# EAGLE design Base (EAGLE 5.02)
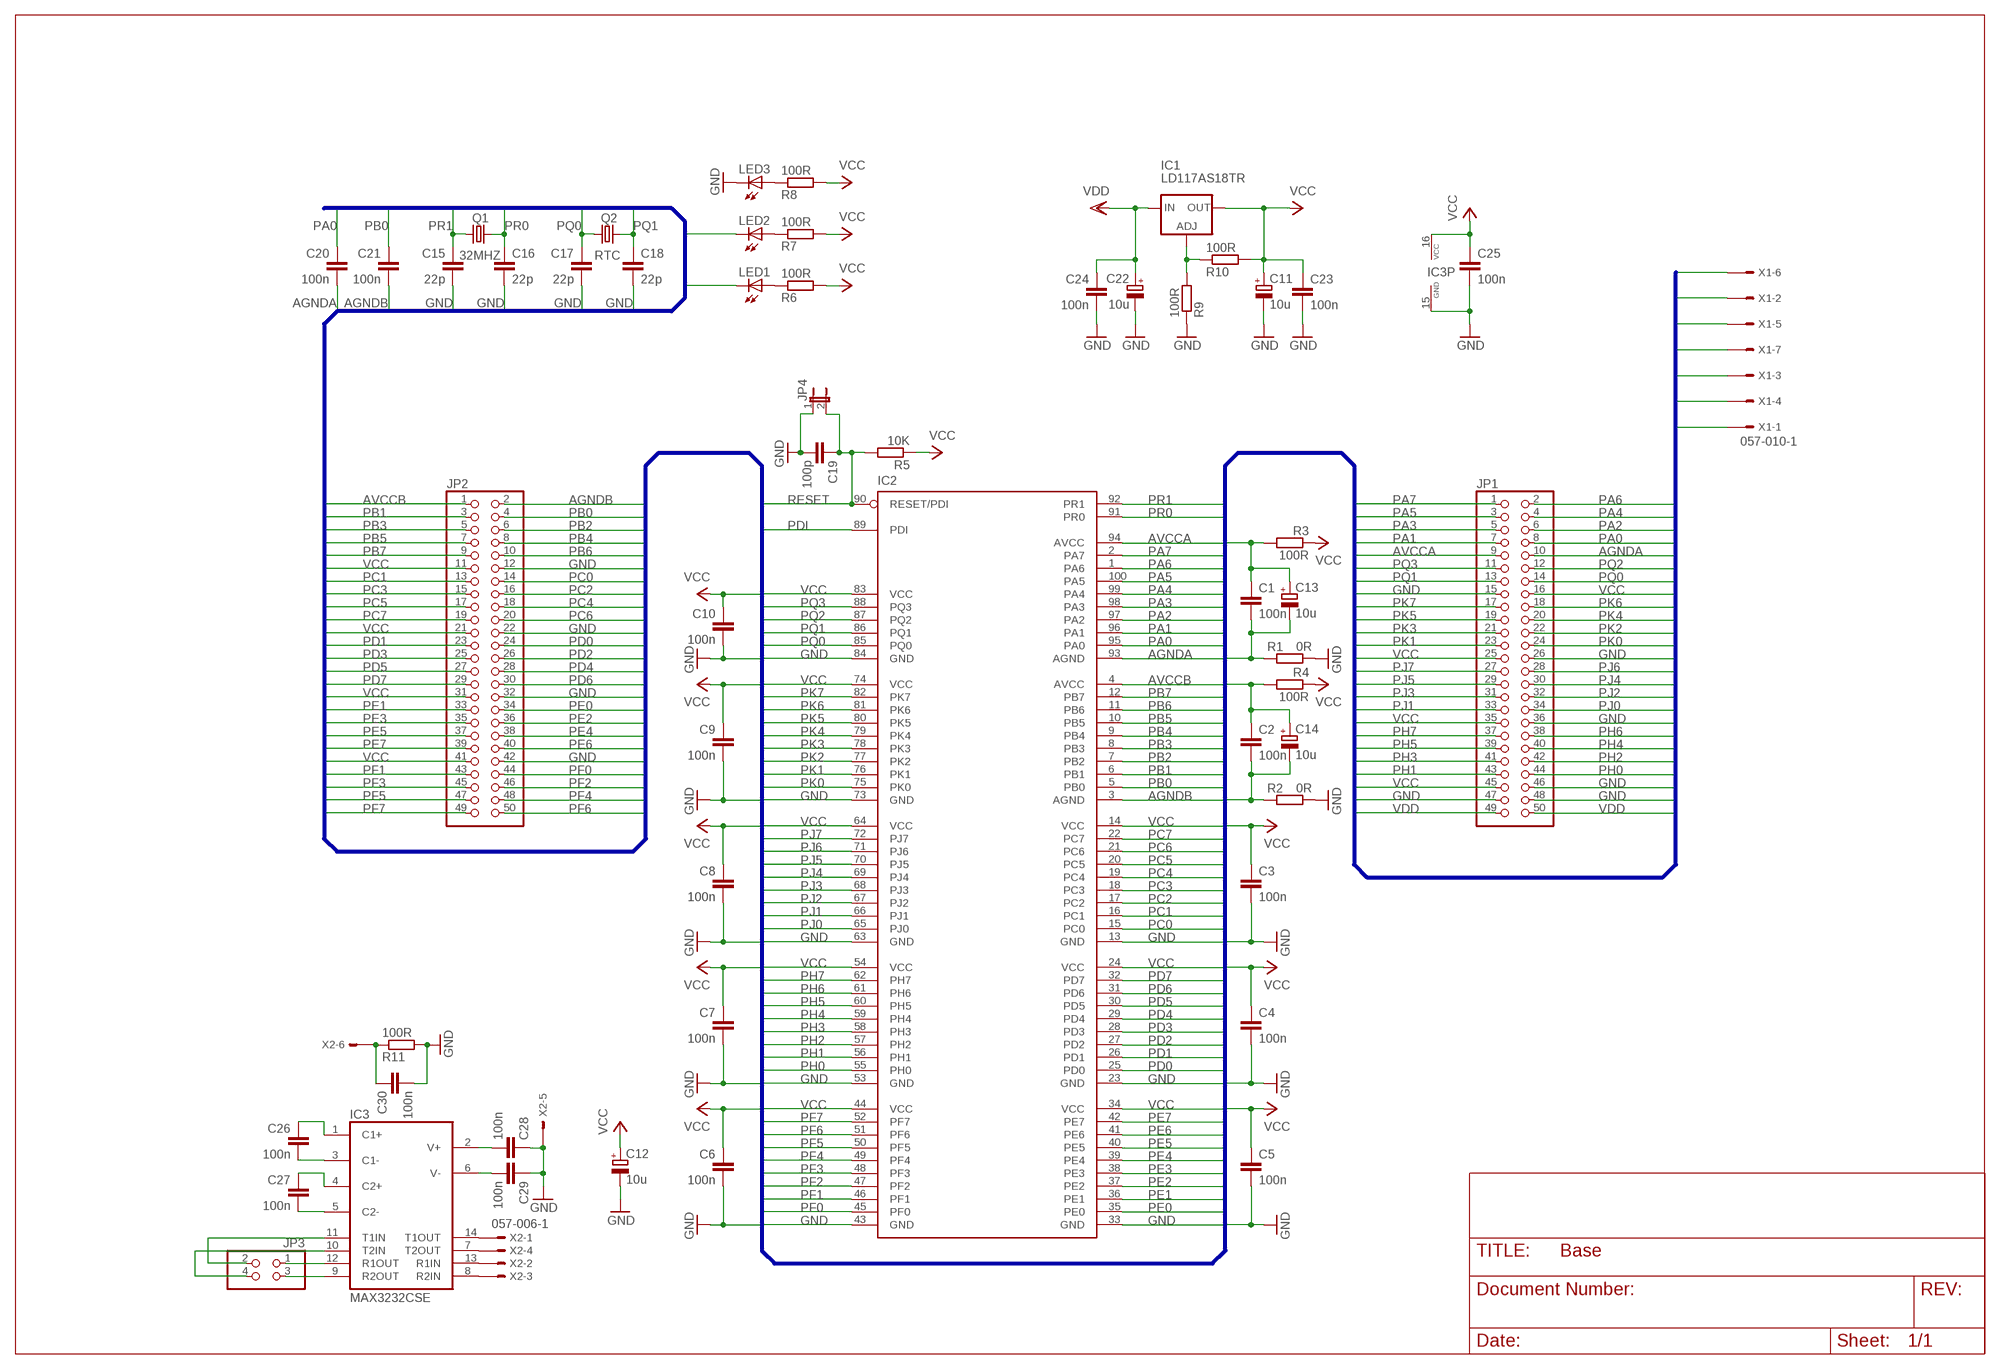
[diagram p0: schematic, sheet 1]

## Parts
C1  100n  C-EUC0603  [C0603]
C2  100n  C-EUC0603  [C0603]
C3  100n  C-EUC0603  [C0603]
C4  100n  C-EUC0603  [C0603]
C5  100n  C-EUC0603  [C0603]
C6  100n  C-EUC0603  [C0603]
C7  100n  C-EUC0603  [C0603]
C8  100n  C-EUC0603  [C0603]
C9  100n  C-EUC0603  [C0603]
C10  100n  C-EUC0603  [C0603]
C11  10u  CPOL-EUC/6032-28R  [C/6032-28R]
C12  10u  CPOL-EUC/6032-28R  [C/6032-28R]
C13  10u  CPOL-EUC/6032-28R  [C/6032-28R]
C14  10u  CPOL-EUC/6032-28R  [C/6032-28R]
C15  22p  C-EUC0603  [C0603]
C16  22p  C-EUC0603  [C0603]
C17  22p  C-EUC0603  [C0603]
C18  22p  C-EUC0603  [C0603]
C19  100p  C-EUC0603  [C0603]
C20  100n  C-EUC0603  [C0603]
C21  100n  C-EUC0603  [C0603]
C22  10u  CPOL-EUC/6032-28R  [C/6032-28R]
C23  100n  C-EUC0603  [C0603]
C24  100n  C-EUC0603  [C0603]
C25  100n  C-EUC0603  [C0603]
C26  100n  C-EUC0603  [C0603]
C27  100n  C-EUC0603  [C0603]
C28  100n  C-EUC0603  [C0603]
C29  100n  C-EUC0603  [C0603]
C30  100n  C-EUC0603  [C0603]
IC1  LD117AS18TR  [SOT223]
IC2  XMEGA128A1-A  [TQFP100]
IC3  MAX3232CSE  [SO16]
JP1  PINHD-2X25  [2X25]
JP2  PINHD-2X25  [2X25]
JP3  PINHD-2X2  [2X02]
JP4  JP1E  [JP1]
LED1  LEDCHIP-LED0805  [CHIP-LED0805]
LED2  LEDCHIP-LED0805  [CHIP-LED0805]
LED3  LEDCHIP-LED0805  [CHIP-LED0805]
Q1  32MHZ  CRYSTALHC49UP  [HC49UP]
Q2  RTC  CRYSTALHC49UP  [HC49UP]
R1  0R  R-EU_R0603  [R0603]
R2  0R  R-EU_R0603  [R0603]
R3  100R  R-EU_R0603  [R0603]
R4  100R  R-EU_R0603  [R0603]
R5  10K  R-EU_R0603  [R0603]
R6  100R  R-EU_R0603  [R0603]
R7  100R  R-EU_R0603  [R0603]
R8  100R  R-EU_R0603  [R0603]
R9  100R  R-EU_R0603  [R0603]
R10  100R  R-EU_R0603  [R0603]
R11  100R  R-EU_R0603  [R0603]
X1  057-010-1  [057-010-1]
X2  057-006-1  [057-006-1]

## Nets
AGNDA: C1.2 C13.- C20.2 IC2.93(AGND1) JP1.10 R1.2
AGNDB: C2.2 C14.- C21.2 IC2.3(AGND2) JP2.2 R2.2
AVCCA: C1.1 C13.+ IC2.94(AVCC1) JP1.9 R3.2
AVCCB: C2.1 C14.+ IC2.4(AVCC2) JP2.1 R4.2
GND: C3.2 C4.2 C5.2 C6.2 C7.2 C8.2 C9.2 C10.2 C11.- C12.- C15.2 C16.2 C17.2 C18.2 C19.2 C22.- C23.2 C24.2 C25.2 C28.1 C29.1 C30.2 IC2.13(GND1) IC2.23(GND2) IC2.33(GND3) IC2.43(GND4) IC2.53(GND5) IC2.63(GND6) IC2.73(GND7) IC2.84(GND8) IC3.15(GND) JP1.15 JP1.26 JP1.36 JP1.46 JP1.47 JP1.48 JP2.12 JP2.22 JP2.32 JP2.42 JP4.1 LED3.C R1.1 R2.1 R9.1 R11.2 X1.6 X2.5
N$1: LED1.A R6.1
N$2: LED2.A R7.1
N$3: LED3.A R8.1
N$4: IC1.1(ADJ) R9.2 R10.1
N$5: C26.2 IC3.3(C1-)
N$6: C27.1 IC3.4(C2+)
N$7: C27.2 IC3.5(C2-)
N$8: C26.1 IC3.1(C1+)
N$9: C28.2 IC3.2(V+)
N$10: C29.2 IC3.6(V-)
N$11: IC3.7(T2OUT) X2.4
N$12: IC3.8(R2IN) X2.3
N$13: IC3.14(T1OUT) X2.1
N$14: IC3.13(R1IN) X2.2
N$15: IC3.11(T1IN) JP3.2
N$16: IC3.10(T2IN) JP3.4
N$17: IC3.12(R1OUT) JP3.1
N$18: IC3.9(R2OUT) JP3.3
N$36: C30.1 R11.1 X2.6
PA0: C20.1 IC2.95(PA0) JP1.8
PA1: IC2.96(PA1) JP1.7
PA2: IC2.97(PA2) JP1.6
PA3: IC2.98(PA3) JP1.5
PA4: IC2.99(PA4) JP1.4
PA5: IC2.100(PA5) JP1.3
PA6: IC2.1(PA6) JP1.2
PA7: IC2.2(PA7) JP1.1
PB0: C21.1 IC2.5(PB0) JP2.4
PB1: IC2.6(PB1) JP2.3
PB2: IC2.7(PB2) JP2.6
PB3: IC2.8(PB3) JP2.5
PB4: IC2.9(PB4) JP2.8 X1.1
PB5: IC2.10(PB5) JP2.7 X1.4
PB6: IC2.11(PB6) JP2.10 X1.3
PB7: IC2.12(PB7) JP2.9 X1.7
PC0: IC2.15(PC0) JP2.14
PC1: IC2.16(PC1) JP2.13
PC2: IC2.17(PC2) JP2.16
PC3: IC2.18(PC3) JP2.15
PC4: IC2.19(PC4) JP2.18
PC5: IC2.20(PC5) JP2.17
PC6: IC2.21(PC6) JP2.20
PC7: IC2.22(PC7) JP2.19
PD0: IC2.25(PD0) JP2.24
PD1: IC2.26(PD1) JP2.23
PD2: IC2.27(PD2) JP2.26
PD3: IC2.28(PD3) JP2.25
PD4: IC2.29(PD4) JP2.28
PD5: IC2.30(PD5) JP2.27
PD6: IC2.31(PD6) JP2.30
PD7: IC2.32(PD7) JP2.29
PDI: IC2.89(PDI)
PE0: IC2.35(PE0) JP2.34
PE1: IC2.36(PE1) JP2.33
PE2: IC2.37(PE2) JP2.36
PE3: IC2.38(PE3) JP2.35
PE4: IC2.39(PE4) JP2.38
PE5: IC2.40(PE5) JP2.37
PE6: IC2.41(PE6) JP2.40
PE7: IC2.42(PE7) JP2.39
PF0: IC2.45(PF0) JP2.44
PF1: IC2.46(PF1) JP2.43
PF2: IC2.47(PF2) JP2.46
PF3: IC2.48(PF3) JP2.45
PF4: IC2.49(PF4) JP2.48
PF5: IC2.50(PF5) JP2.47
PF6: IC2.51(PF6) JP2.50
PF7: IC2.52(PF7) JP2.49
PH0: IC2.55(PH0) JP1.44
PH1: IC2.56(PH1) JP1.43
PH2: IC2.57(PH2) JP1.42
PH3: IC2.58(PH3) JP1.41
PH4: IC2.59(PH4) JP1.40
PH5: IC2.60(PH5) JP1.39
PH6: IC2.61(PH6) JP1.38
PH7: IC2.62(PH7) JP1.37
PJ0: IC2.65(PJ0) JP1.34
PJ1: IC2.66(PJ1) JP1.33
PJ2: IC2.67(PJ2) JP1.32
PJ3: IC2.68(PJ3) JP1.31
PJ4: IC2.69(PJ4) JP1.30
PJ5: IC2.70(PJ5) JP1.29
PJ6: IC2.71(PJ6) JP1.28
PJ7: IC2.72(PJ7) JP1.27
PK0: IC2.75(PK0) JP1.24
PK1: IC2.76(PK1) JP1.23
PK2: IC2.77(PK2) JP1.22
PK3: IC2.78(PK3) JP1.21
PK4: IC2.79(PK4) JP1.20
PK5: IC2.80(PK5) JP1.19
PK6: IC2.81(PK6) JP1.18
PK7: IC2.82(PK7) JP1.17
PQ0: C17.1 IC2.85(PQ0) JP1.14 Q2.1
PQ1: C18.1 IC2.86(PQ1) JP1.13 Q2.2
PQ2: IC2.87(PQ2) JP1.12 LED1.C
PQ3: IC2.88(PQ3) JP1.11 LED2.C
PR0: C16.1 IC2.91(PR0) Q1.2
PR1: C15.1 IC2.92(PR1) Q1.1
RESET: C19.1 IC2.90(RESET/PDI) JP4.2 R5.2 X1.5
VCC: C3.1 C4.1 C5.1 C6.1 C7.1 C8.1 C9.1 C10.1 C11.+ C12.+ C23.1 C25.1 IC1.4(OUT) IC2.14(VCC1) IC2.24(VCC2) IC2.34(VCC3) IC2.44(VCC4) IC2.54(VCC5) IC2.64(VCC6) IC2.74(VCC7) IC2.83(VCC8) IC3.16(VCC) JP1.16 JP1.25 JP1.35 JP1.45 JP2.11 JP2.21 JP2.31 JP2.41 R3.1 R4.1 R5.1 R6.2 R7.2 R8.2 R10.2 X1.2
VDD: C22.+ C24.1 IC1.3(IN) JP1.49 JP1.50
Unconnected: X1.8 X1.9 X1.10

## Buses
RESET,PDI,PA[0..7],PB[0..7],PC[0..7],PD[0..7],PE[0..7],PF[0..7],PH[0..7],PJ[0..7],PK[0..7],PQ[0..3],PR[0..1],VCC,VDD,GND,AVCCA,AGNDA,AVCCB,AGNDB

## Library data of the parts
C1-C10 C15-C21 C23-C30 = rcl:C-EU: CAPACITOR, European symbol
C11-C14 C22 = rcl:CPOL-EU: POLARIZED CAPACITOR, European symbol
IC1 = v-reg:LD117A?*: Low drop fixed and adjustable positive voltage regulators 1 A Source: http://www.st.com/stonline/products/literature/ds/7194/ld1117axx.pdf
IC2 = hinck:XMEGA128A1: The XMEGA? A1 is a family of low power, high performance and peripheral rich CMOS 8/16-bit microcontrollers based on the AVR® enhanced RISC architecture. By executing powerful instructions in a single clock cycle, the XMEGA A1 achieves throughputs approaching 1 Million Instructions Per Second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
IC3 = maxim:MAX3232*: True RS-232 Transceivers 3.0V to 5.5V, Low-Power up to 1Mbps, Using Four 0.1µF External Capacitors Source: http://pdfserv.maxim-ic.com/en/ds/MAX3222-MAX3241.pdf
JP1 JP2 = pinhead:PINHD-2X25: PIN HEADER
JP3 = pinhead:PINHD-2X2: PIN HEADER
JP4 = jumper:JP1E: JUMPER
LED1-LED3 = led:LED: LED
Q1 Q2 = crystal:CRYSTAL: CRYSTAL
R1-R11 = rcl:R-EU_: RESISTOR, European symbol
X1 = con-panduit:057-010-: CONNECTOR 10-pin series 057 contact pc board low profile headers
X2 = con-panduit:057-006-: CONNECTOR 6-pin series 057 contact pc board low profile headers

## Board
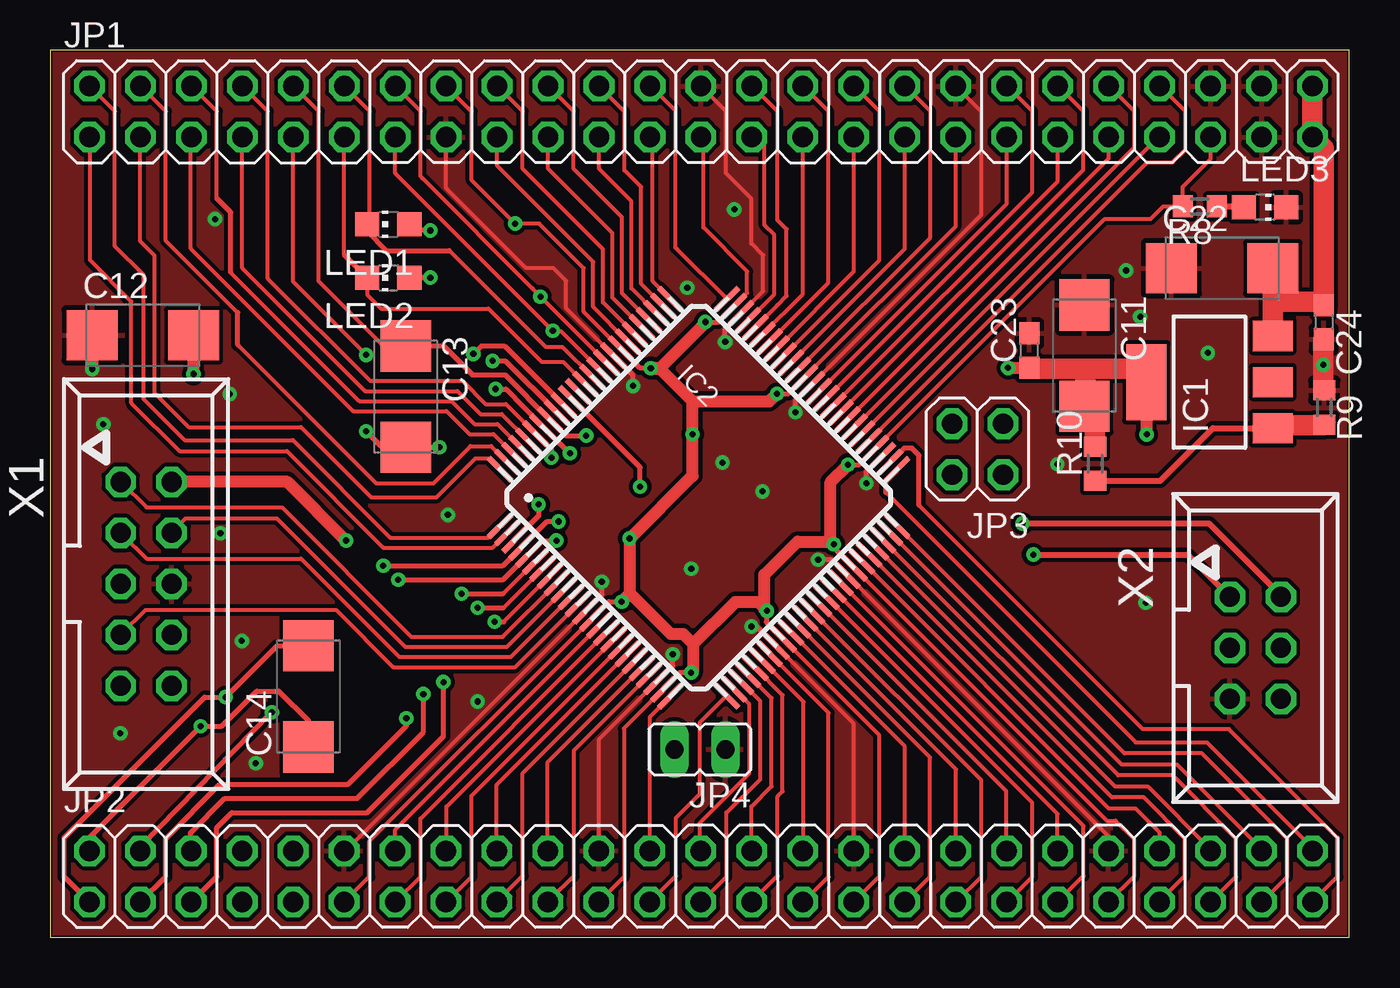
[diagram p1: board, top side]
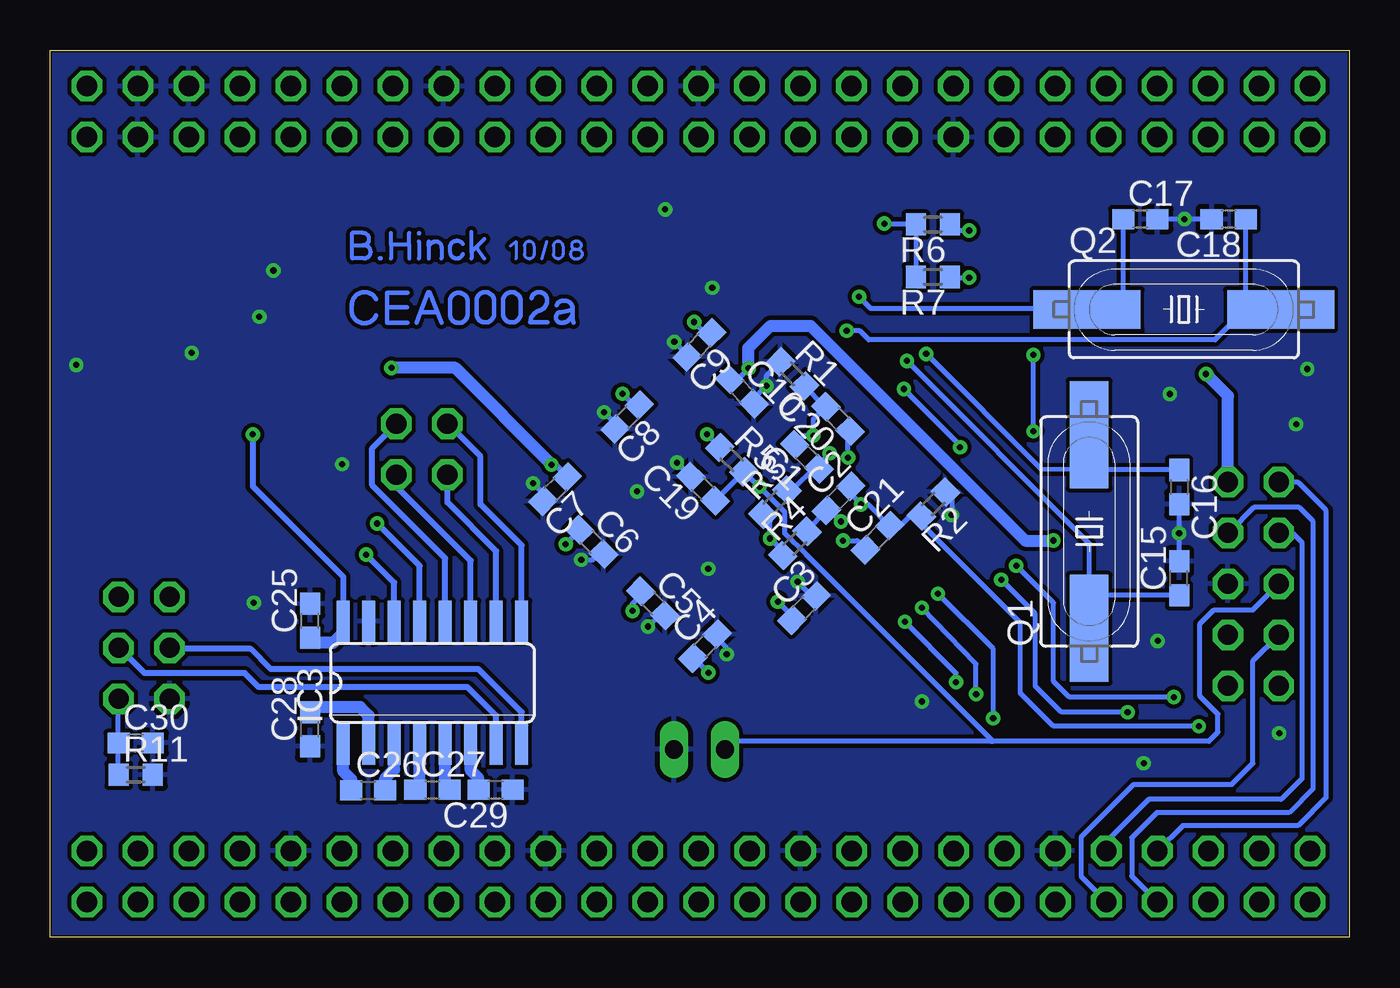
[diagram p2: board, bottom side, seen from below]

Size 64.75 x 44.2 mm. Coordinates in mm from the lower left corner, seen from the top.
Outline: 0,0 64.75,0 64.75,44.2 0,44.2 0,0
Copper layers (1*16): Top 0.035mm / dielectric 1.5mm / Bottom 0.035mm
Design rules "default *": minimum track width 6mil, minimum drill 12mil, track to track 8mil, track to pad 8mil, pad to pad 8mil, via to via 8mil, smd to smd 1mil, copper to edge 4mil, drill to drill 8mil, minimum pad ring 10mil, minimum via ring 8mil, stop-mask expansion 4mil, vias tented up to drill 0mil, thermal gap 10mil

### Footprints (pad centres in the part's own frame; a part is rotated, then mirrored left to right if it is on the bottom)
C0603 = smd 1.1 x 1: 1 -0.85,0; 2 0.85,0
C/6032-28R = smd 2.55 x 2.5: + 2.525,0; - -2.525,0
SOT223 = smd 1.5 x 2: 1 -2.3,-3.15; 2 0,-3.15; 3 2.3,-3.15 | smd 3.8 x 2: 4 0,3.15
TQFP100 = smd 0.28 x 1.6: 1 -6,-8; 2 -5.5,-8; 3 -5,-8; 4 -4.5,-8; 5 -4,-8; 6 -3.5,-8; 7 -3,-8; 8 -2.5,-8; 9 -2,-8; 10 -1.5,-8; 11 -1,-8; 12 -0.5,-8; 13 0,-8; 14 0.5,-8; 15 1,-8; 16 1.5,-8; 17 2,-8; 18 2.5,-8; 19 3,-8; 20 3.5,-8; 21 4,-8; 22 4.5,-8; 23 5,-8; 24 5.5,-8; 25 6,-8; 51 6,8; 52 5.5,8; 53 5,8; 54 4.5,8; 55 4,8; 56 3.5,8; 57 3,8; 58 2.5,8; 59 2,8; 60 1.5,8; 61 1,8; 62 0.5,8; 63 0,8; 64 -0.5,8; 65 -1,8; 66 -1.5,8; 67 -2,8; 68 -2.5,8; 69 -3,8; 70 -3.5,8; 71 -4,8; 72 -4.5,8; 73 -5,8; 74 -5.5,8; 75 -6,8 | smd 1.6 x 0.28: 26 8,-6; 27 8,-5.5; 28 8,-5; 29 8,-4.5; 30 8,-4; 31 8,-3.5; 32 8,-3; 33 8,-2.5; 34 8,-2; 35 8,-1.5; 36 8,-1; 37 8,-0.5; 38 8,0; 39 8,0.5; 40 8,1; 41 8,1.5; 42 8,2; 43 8,2.5; 44 8,3; 45 8,3.5; 46 8,4; 47 8,4.5; 48 8,5; 49 8,5.5; 50 8,6; 76 -8,6; 77 -8,5.5; 78 -8,5; 79 -8,4.5; 80 -8,4; 81 -8,3.5; 82 -8,3; 83 -8,2.5; 84 -8,2; 85 -8,1.5; 86 -8,1; 87 -8,0.5; 88 -8,0; 89 -8,-0.5; 90 -8,-1; 91 -8,-1.5; 92 -8,-2; 93 -8,-2.5; 94 -8,-3; 95 -8,-3.5; 96 -8,-4; 97 -8,-4.5; 98 -8,-5; 99 -8,-5.5; 100 -8,-6
SO16 = smd 0.66 x 2.032: 1 -4.445,-3.073; 2 -3.175,-3.073; 3 -1.905,-3.073; 4 -0.635,-3.073; 5 0.635,-3.073; 6 1.905,-3.073; 7 3.175,-3.073; 8 4.445,-3.073; 9 4.445,3.073; 10 3.175,3.073; 11 1.905,3.073; 12 0.635,3.073; 13 -0.635,3.073; 14 -1.905,3.073; 15 -3.175,3.073; 16 -4.445,3.073
2X25 = drill 1.016 octagon: 1 -30.48,-1.27; 2 -30.48,1.27; 3 -27.94,-1.27; 4 -27.94,1.27; 5 -25.4,-1.27; 6 -25.4,1.27; 7 -22.86,-1.27; 8 -22.86,1.27; 9 -20.32,-1.27; 10 -20.32,1.27; 11 -17.78,-1.27; 12 -17.78,1.27; 13 -15.24,-1.27; 14 -15.24,1.27; 15 -12.7,-1.27; 16 -12.7,1.27; 17 -10.16,-1.27; 18 -10.16,1.27; 19 -7.62,-1.27; 20 -7.62,1.27; 21 -5.08,-1.27; 22 -5.08,1.27; 23 -2.54,-1.27; 24 -2.54,1.27; 25 0,-1.27; 26 0,1.27; 27 2.54,-1.27; 28 2.54,1.27; 29 5.08,-1.27; 30 5.08,1.27; 31 7.62,-1.27; 32 7.62,1.27; 33 10.16,-1.27; 34 10.16,1.27; 35 12.7,-1.27; 36 12.7,1.27; 37 15.24,-1.27; 38 15.24,1.27; 39 17.78,-1.27; 40 17.78,1.27; 41 20.32,-1.27; 42 20.32,1.27; 43 22.86,-1.27; 44 22.86,1.27; 45 25.4,-1.27; 46 25.4,1.27; 47 27.94,-1.27; 48 27.94,1.27; 49 30.48,-1.27; 50 30.48,1.27
2X02 = drill 1.016 octagon: 1 -1.27,-1.27; 2 -1.27,1.27; 3 1.27,-1.27; 4 1.27,1.27
JP1 = drill 0.914 long: 1 0,-1.27; 2 0,1.27
CHIP-LED0805 = smd 1.2 x 1.2: A 0,-1.05; C 0,1.05
HC49UP = smd 5.334 x 1.93: 1 -4.826,0; 2 4.826,0
R0603 = smd 1 x 1.1: 1 -0.85,0; 2 0.85,0
057-010-1 = drill 1 octagon: 1 -5.08,-1.27; 2 -5.08,1.27; 3 -2.54,-1.27; 4 -2.54,1.27; 5 0,-1.27; 6 0,1.27; 7 2.54,-1.27; 8 2.54,1.27; 9 5.08,-1.27; 10 5.08,1.27
057-006-1 = drill 1 octagon: 1 -2.54,-1.27; 2 -2.54,1.27; 3 0,-1.27; 4 0,1.27; 5 2.54,-1.27; 6 2.54,1.27

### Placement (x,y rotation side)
C1  27.04,23.95 135 bottom
C2  25.46,21.87 45 bottom
C3  27.17,16.41 45 bottom
C4  32.11,14.51 45 bottom
C5  34.71,16.64 315 bottom
C6  37.77,19.7 315 bottom
C7  39.58,22.33 225 bottom
C8  35.99,25.92 225 bottom
C9  32.39,29.52 225 bottom
C10  30.28,27.19 315 bottom
C11  51.55,28.98 270 top
C12  4.62,30 0 top
C13  17.73,26.94 270 top
C14  12.87,12.01 90 top
C15  8.48,17.88 90 bottom
C16  8.48,22.43 270 bottom
C17  10.42,35.78 0 bottom
C18  6.02,35.78 180 bottom
C19  32.22,22.35 135 bottom
C20  25.48,25.83 135 bottom
C21  23.51,19.91 45 bottom
C22  58.41,33.34 0 top
C23  48.8,29.24 90 top
C24  63.47,30.65 270 top
C25  51.79,15.77 90 bottom
C26  48.9,7.33 0 bottom
C27  45.7,7.35 0 bottom
C28  51.8,10.37 90 bottom
C29  42.55,7.35 180 bottom
C30  60.48,9.68 0 bottom
IC1  57.78,27.66 90 top
IC2  32.32,21.91 315 top
IC3  45.7,12.68 0 bottom
JP1  32.44,41.14 0 top
JP2  32.43,3.04 0 top
JP3  46.22,24.32 180 top
JP4  32.39,9.37 90 top
LED1  16.85,35.52 90 top
LED2  16.85,32.87 90 top
LED3  60.55,36.37 270 top
Q1  12.96,20.21 90 bottom
Q2  8.25,31.28 0 bottom
R1  27.75,28.07 315 bottom
R2  20.73,21.59 225 bottom
R3  28.62,21.67 45 bottom
R4  27.63,19.62 45 bottom
R5  30.78,23.8 315 bottom
R6  20.75,35.52 180 bottom
R7  20.75,32.9 180 bottom
R8  57.3,36.42 180 top
R9  63.5,26.4 270 top
R10  52.08,23.59 90 top
R11  60.48,8.1 0 bottom
X1  4.78,17.61 270 top
X2  60.07,14.42 270 top

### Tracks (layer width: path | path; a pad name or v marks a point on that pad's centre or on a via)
AGNDA  (via drill 0.3)
  Top 0.203: 16.61,29.46 13.39,32.68 13.39,41.15 12.14,42.39
  Top 0.254: v26.71,25 25.7,25 IC2.93 22.68,28.02 21.05,28.02 19.6,29.47 C13.- 16.61,29.46 | JP1.10 12.12,42.39 12.14,42.39
  Bottom 0.254: C1.2 27.2,25 v26.71,25 26.71,25.8 C20.2 26.1,26.45 26.13,26.45 R1.2
AGNDB  (via drill 0.3, 0.3 pad 0.3)
  Top 0.254: IC2.3 24.35,21 v24.35,21.57 | JP2.2 1.95,4.97 v7.5,10.52 8.55,10.52 10.3,12.27 11.4,12.27 12.87,10.8 C14.-
  Bottom 0.254: C2.2 25.05,22.27 v24.35,21.57 23.96,21.57 C21.2 22.9,20.53 22.51,20.38 21.85,21.04 21.55,21.11 R2.2 21.35,20.97 21.35,20.62 16.4,15.67 16.4,12.17 14.75,10.52 v7.5,10.52
AVCCA  (via drill 0.3, 0.3 pad 0.3)
  Top 0.203: v15.75,29.02 12.12,32.65 JP1.9
  Top 0.254: v25.9,24.11 25.87,24.11 IC2.94 22.72,27.32 v22.2,27.32 | v19.4,24.42 C13.+ 17.61,24.41 17.6,24.42 16.55,24.42 v15.75,25.22 | JP1.9
  Bottom 0.254: 26.57,23.48 26.54,23.48 v25.9,24.11 | 26.57,23.48 C1.1 | 26.57,23.48 27.77,22.27 R3.2 | v22.2,27.32 19.45,24.57 v19.4,24.42 | v15.75,25.22 v15.75,29.02
AVCCB  (via drill 0.3, 0.3 pad 0.3)
  Top 0.254: v25.34,20.72 24.77,20.72 IC2.4 22.57,18.52 v16.6,18.52 | JP2.1 | JP2.1 0.7,3.02 0.7,4.97 7.7,11.97 v8.75,11.97 11.31,14.53 C14.+
  Bottom 0.254: v25.34,20.72 25.97,21.36 C2.1 27.07,20.26 R4.2 | v16.6,18.52 14.75,16.67 14.75,12.77 13.95,11.97 v8.75,11.97
GND  (via drill 0.3, 0.3 pad 0.3)
  Top 0.203: JP2.22 27.36,9.87 IC2.23 | JP2.32 40.06,10.64 IC2.33 | JP2.42 52.76,5.01 38.95,18.81 | JP1.15 19.74,37.32 23.72,33.34 25.08,33.34 25.72,32.7 25.72,31.34 IC2.84 | JP1.26 33.68,41.17 33.68,38.08 34.95,36.8 34.95,34.57 35.53,33.98 35.53,32.19 IC2.73 | JP1.36 46.41,41.14 46.41,35.99 IC2.63 | JP2.12 14.66,4.29 14.71,4.29 IC2.13
  Top 0.254: IC2.73 33.65,30.3 v33.65,29.66 | IC2.63 37.15,26.73 v37.15,26.16 | IC2.53 40.68,23.19 v40.68,22.63 | IC2.43 38.95,18.81 v38.28,18.81 | IC2.33 35.21,15.49 v34.95,15.49 | IC2.23 31.03,13.54 v31.03,14.11 | IC2.13 27.49,17.08 v27.49,17.71 | IC2.84 29.05,28.01 v29.05,27.47
  Top 0.61: C12.- v2.1,28.32
  Top 1.016: C24.2 63.45,29.78 v63.45,28.52 63.45,27.3 R9.1
  Bottom 0.254: C9.2 33.01,28.93 33.01,29.03 v33.65,29.66 | C8.2 36.58,25.6 v37.15,26.16 | C7.2 40.19,22.13 v40.68,22.63 | v38.28,18.81 37.71,18.81 37.39,19.13 37.18,19.13 37.18,19.11 C6.2 | C5.2 34.1,16.05 34.39,16.05 v34.95,15.49 | v31.03,14.11 31.03,14.39 31.52,14.89 31.52,15.1 C4.2 | C3.2 26.86,17.15 26.93,17.15 v27.49,17.71 | C10.2 29.76,26.67 29.76,26.77 v29.05,27.47 29.05,27.98 R1.1 | C17.2 v8.22,35.78 C18.2 | C15.2 v8.48,20.13 C16.2 | C19.2 33.43,23.57 v33.5,23.65 | R2.1 19.82,21.88 v19.82,21.05
  other vias: 9.55,14.77 10.25,8.67 3.5,10.17 8.95,27.07 2.65,25.57 31.75,32.37 34.1,36.27 31.95,18.37 35.5,22.22 50.2,23.57 57.7,29.12 54.6,16.67 54.33,30.92 53.62,33.22 21.3,11.75
  pour Bottom: -0.32,-0.32 -0.32,44.45 65.09,44.45 65.09,-0.32
  pour Top: -0.32,-0.32 -0.32,44.45 65.09,44.45 65.09,-0.32
N$1  (via drill 0.3 pad 0.3)
  Top 0.254: LED1.A 18.2,35.22 v18.95,35.22
  Bottom 0.254: R6.1 19.9,35.22 v18.95,35.22 | R6.1
N$2  (via drill 0.3 pad 0.3)
  Top 0.254: LED2.A | v18.95,32.87 LED2.A
  Bottom 0.254: R7.1 19.9,32.87 v18.95,32.87 | R7.1
N$3
  Top 0.305: LED3.A | R8.1 59.45,36.42 LED3.A
N$4
  Top 0.305: R10.1 55.32,22.74 57.95,25.37 60.9,25.37 60.91,25.36 IC1.1
  Top 1.016: IC1.1 60.95,25.38 60.95,25.52 63.47,25.52 R9.2
N$5
  Bottom 0.61: IC3.3 47.6,8.36 48.05,7.92 C26.2
N$6
  Bottom 0.61: C27.1 46.55,7.37 46.34,7.58 IC3.4
N$7
  Bottom 0.61: C27.2 44.85,7.37 45.06,7.58 IC3.5
N$8
  Bottom 0.61: IC3.1 50.15,8.26 49.75,7.87 C26.1
N$9
  Bottom 0.61: IC3.2 48.88,11.04 49.3,11.47 51.55,11.47 C28.2 | C28.2
N$10
  Bottom 0.61: IC3.6 43.8,8.31 43.4,7.92 C29.2
N$11
  Bottom 0.305: IC3.7 42.52,11.04 43.95,12.47 54.35,12.47 55.05,13.17 60.05,13.17 61.25,14.37 61.29,14.37 X2.4
N$12
  Bottom 0.305: IC3.8 41.26,11.22 43.4,13.37 53.75,13.37 54.75,14.37 58.75,14.37 X2.3
N$13  (via drill 0.3 pad 0.3)
  Top 0.305: X2.1 56.7,19.07 v49,19.07
  Bottom 0.305: IC3.14 47.6,17.67 v49,19.07
N$14  (via drill 0.3 pad 0.3)
  Top 0.305: X2.2 61.34,17.01 61.35,17.02 57.75,20.62 v48.45,20.62
  Bottom 0.305: IC3.13 46.34,18.5 v48.45,20.62
N$15
  Bottom 0.305: IC3.11 43.8,18.76 47.5,22.47 47.5,22.87 47.49,22.88 JP3.2
N$16
  Bottom 0.305: IC3.10 42.52,19.24 44.95,21.67 JP3.4
N$17
  Bottom 0.305: IC3.12 45.06,18.88 48.7,22.52 48.7,24.37 47.49,25.58 JP3.1
N$18
  Bottom 0.305: IC3.9 41.26,19.52 43.3,21.57 43.3,23.97 44.92,25.59 JP3.3
N$19
  Bottom 0.203: 49.16,34.48 49.11,34.48 arc180 49.11,33.82 49.69,33.82 49.69,34.48 | 49.16,34.48 arc-180 49.16,35.09 49.69,35.09 49.69,34.48 | 49.69,34.48 49.16,34.48
N$20
  Bottom 0.203: 48.32,33.85 48.27,33.85 48.27,33.82 48.32,33.82 48.32,33.85
N$21
  Bottom 0.203: 47.76,34.51 47.76,35.09 | 47.76,34.51 47.76,33.82 | 46.85,34.51 47.76,34.51 | 46.85,34.51 46.85,33.82 | 46.85,34.51 46.85,35.09
N$22
  Bottom 0.203: 46.37,35.09 46.34,35.09 46.34,35.07 46.37,35.07 46.37,35.09
N$23
  Bottom 0.203: 46.37,34.66 46.37,33.82
N$24
  Bottom 0.203: 45.25,33.82 45.25,34.38 arc-111 45.6,34.66 arc-44 45.88,34.43 | 45.88,34.43 45.88,33.82 | 45.88,34.43 45.88,34.66
N$25
  Bottom 0.203: 44.18,34.53 arc-139 44.82,34.43 44.82,34.13 arc-159 44.18,34.05
N$26
  Bottom 0.203: 43.75,34.15 43.75,35.14 | 43.75,34.15 43.75,33.82 | 43.54,34.37 43.75,34.15 | 43.54,34.37 43.11,34.79 | 43.11,33.82 43.49,34.38 43.47,34.38 43.47,34.37 43.54,34.37
N$27
  Bottom 0.203: 49.72,31.52 49.71,31.52 49.71,31.46 49.72,31.46
  Bottom 0.229: 49.72,31.46 49.72,31.28 | 49.72,31.46 49.72,31.52 49.72,31.54 arc150 48.5,31.79 | 49.72,31.46 49.72,31.16 arc-152 48.5,31
N$28
  Bottom 0.152: 41.11,34.44 41.11,34.04 arc-180 40.63,34.04 40.63,34.44 arc-180 41.11,34.44
N$29
  Bottom 0.229: 46.92,32.12 47.97,32.12 47.97,31.38 | 47.97,31.38 47.97,30.62 46.92,30.62 | 47.97,31.38 46.95,31.38
N$30
  Bottom 0.203: 46.24,31.16 46.29,31.16 | 46.26,31.16 46.24,31.16 | 46.24,31.16 46.24,31.14
  Bottom 0.229: 46.49,30.62 46.29,31.16 45.91,32.15 45.83,32.15 45.25,30.62 | 45.45,31.16 46.26,31.16
N$31
  Bottom 0.152: 41.82,34.44 41.54,34.68 41.54,33.81
N$32
  Bottom 0.229: 44.83,31.66 44.83,31.04 arc-180 43.94,31.06 43.94,31.69 arc-180 44.83,31.66
N$33
  Bottom 0.152: 40.01,34.68 40.25,33.81
N$34
  Bottom 0.229: 43.51,31.69 43.51,31.06 arc-180 42.62,31.09 42.62,31.71 arc-180 43.51,31.69
N$35
  Bottom 0.229: 42.18,31.69 42.18,31.06 arc-180 41.3,31.09 41.3,31.71 arc-180 42.18,31.69
N$36
  Bottom 0.254: R11.1 61.36,8.12 61.36,9.68 C30.1 61.36,9.71 61.36,11.86 X2.6
N$37
  Bottom 0.203: 38.72,31.28 38.72,31.26
  Bottom 0.229: 38.72,31.26 38.72,31 arc-15 38.67,30.62 | 38.72,31.28 arc108 39.3,30.62 arc174 39.28,31.16 arc-21 38.72,31.28 | 38.72,31.28 38.72,31.36 arc-90 39.08,31.71 39.2,31.71 arc-74 39.51,31.48
N$38
  Bottom 0.152: 39.67,34.44 39.67,34.04 arc-180 39.19,34.04 39.19,34.44 arc-180 39.67,34.44
N$39
  Bottom 0.152: 38.46,34.28 arc-180 38.48,34.68 38.56,34.68 arc-180 38.56,34.28 | 38.46,34.28 38.59,34.28 arc-180 38.56,33.81 38.48,33.81 arc-180 38.46,34.28
N$40
  Bottom 0.229: 39.95,30.64 40.83,30.64 40.82,30.64 40.82,30.69 arc66 40.36,31.23 arc-77 39.98,31.76 arc-164 40.77,31.84
PA0  (via drill 0.3)
  Top 0.203: IC2.95 22.71,26.57 21.7,26.57 20.55,27.72 15.95,27.72 10.85,32.82 10.85,41.15 9.6,42.39
  Top 0.254: IC2.95 24.98,24.3 v24.98,23.9 | JP1.8 9.58,42.39 9.6,42.39
  Bottom 0.254: C20.1 24.98,25.13 v24.98,23.9
PA1
  Top 0.203: IC2.96 22.5,26.07 21.45,26.07 20.3,27.22 15.7,27.22 9.58,33.34 JP1.7
  Top 0.254: JP1.7
PA2
  Top 0.203: IC2.97 22.3,25.57 21.15,25.57 20,26.72 15.4,26.72 9,33.12 | 8.31,36.81 8.31,41.15 7.06,42.39
  Top 0.254: 9,33.12 9,36.12 8.31,36.81 | JP1.6 7.04,42.39 7.06,42.39
PA3
  Top 0.203: IC2.98 22.09,25.07 20.9,25.07 19.75,26.22 15.1,26.22 7.01,34.31 7.01,39.85
  Top 0.254: 7.01,39.85 JP1.5
PA4
  Top 0.203: IC2.99 21.98,24.47 20.95,24.47 19.1,22.62 16.25,22.62 9.35,29.52 | 9.35,31.12 5.77,34.7 5.77,41.15 4.55,42.37
  Top 0.254: 9.35,29.52 9.35,31.12 | 4.55,42.37 4.54,42.37 JP1.4
PA5
  Top 0.203: IC2.100 21.88,23.87 21.2,23.87 19.25,21.92 16,21.92 12.5,25.42 6.9,25.42 5.2,27.12 5.2,33.97 4.5,34.67 JP1.3
  Top 0.254: JP1.3
PA6
  Top 0.203: IC2.1 21.85,19.92 16.95,19.92 12.1,24.77 6.7,24.77 4.65,26.82 4.65,33.02 3.23,34.44 3.23,41.15 2.01,42.37
  Top 0.254: JP1.2 1.98,42.39 2.01,42.39 2.01,42.37
PA7
  Top 0.203: IC2.2 22.05,19.42 16.6,19.42 11.8,24.22 6.45,24.22 4.05,26.62 4.05,31.67 1.98,33.73 1.98,39.85
  Top 0.254: 1.98,39.85 JP1.1
PB0  (via drill 0.3, 0.3 pad 0.3)
  Top 0.254: v25.23,19.77 24.52,19.77 IC2.5 22.58,17.82 v17.35,17.82 | v11.05,11.22 4.5,4.52 JP2.4 | JP2.4
  Bottom 0.254: v25.23,19.77 24.52,19.77 24.13,19.38 24.13,19.33 C21.1 | v17.35,17.82 15.65,16.12 15.65,12.52 14.35,11.22 v11.05,11.22
PB1  (via drill 0.3 pad 0.3)
  Top 0.203: 22.58,17.12 IC2.6
  Top 0.254: JP2.3 5.75,3.03 5.75,4.92 8.45,7.62 14.85,7.62 17.75,10.52 v17.75,10.92 | v20.5,17.12 22.58,17.12
  Bottom 0.254: v17.75,10.92 17.75,14.37 v20.5,17.12
PB2  (via drill 0.3 pad 0.3)
  Top 0.203: 22.59,16.42 IC2.7
  Top 0.254: v21.3,16.42 22.59,16.42 | v18.6,12.12 18.6,10.22 15.3,6.92 8.7,6.92 7,5.22 7,4.42 7.03,4.39 JP2.6
  Bottom 0.254: v21.3,16.42 18.6,13.62 v18.6,12.12
PB3  (via drill 0.3 pad 0.3)
  Top 0.203: 22.6,15.72 IC2.8
  Top 0.254: v22.15,15.72 22.6,15.72 | v19.6,12.72 19.6,10.02 15.8,6.22 9.05,6.22 8.3,5.47 8.3,3.02 7.05,1.77 JP2.5
  Bottom 0.254: v22.15,15.72 19.6,13.17 v19.6,12.72
PB4
  Top 0.203: 3.55,22.67 4.8,21.42 11.55,21.42 18,14.97 22.55,14.97 IC2.9
  Top 0.254: 3.55,22.67 3.53,22.67 X1.1
  Bottom 0.254: JP2.8 8.31,5.57 2.55,5.57 1.15,6.97 1.15,21.27 2.55,22.67 3.49,22.67 X1.1
PB5
  Top 0.203: 6.05,20.17 6.75,20.87 11.3,20.87 17.7,14.47 22.76,14.47 IC2.10
  Top 0.254: 6.05,20.17 X1.4
  Bottom 0.254: JP2.7 10.85,3.05 10.85,4.97 9.6,6.22 3,6.22 1.8,7.42 1.8,20.72 2.5,21.42 4.75,21.42 6,20.17 6.03,20.17 X1.4
PB6
  Top 0.203: 3.55,20.12 4.8,18.87 12.5,18.87 17.4,13.97 22.97,13.97 IC2.11
  Top 0.254: 3.55,20.12 3.54,20.12 X1.3
  Bottom 0.254: JP2.10 12.1,4.77 10,6.87 3.4,6.87 2.35,7.92 2.35,19.67 2.85,20.17 3.49,20.17 X1.3
PB7
  Top 0.203: 3.55,15.12 4.75,16.32 14.25,16.32 17.1,13.47 23.18,13.47 IC2.12
  Top 0.254: 3.55,15.12 3.55,15.11 X1.7
  Bottom 0.254: JP2.9 13.35,3.01 13.35,5.02 10.75,7.62 5.85,7.62 4.8,8.67 4.8,13.77 X1.7 | X1.7 | X1.7
PC0
  Top 0.203: IC2.15 17.2,5.37 JP2.14
  Top 0.254: JP2.14
PC1
  Top 0.203: IC2.16 18.45,5.91 18.45,3.02 17.25,1.82
  Top 0.254: 17.25,1.82 17.24,1.82 JP2.13
PC2
  Top 0.203: IC2.17 19.75,6.51 19.75,4.33
  Top 0.254: JP2.16 19.75,4.33
PC3
  Top 0.203: IC2.18 21,7.05 21,3.02 19.75,1.77
  Top 0.254: JP2.15 19.75,1.77 | JP2.15
PC4
  Top 0.203: IC2.19 22.25,7.59 22.25,4.33
  Top 0.254: JP2.18 22.25,4.33
PC5
  Top 0.203: IC2.20 23.55,8.19 23.55,3.07 22.3,1.82
  Top 0.254: 22.3,1.82 22.3,1.8 JP2.17
PC6
  Top 0.203: IC2.21 24.8,8.73 JP2.20
  Top 0.254: JP2.20
PC7
  Top 0.203: IC2.22 26.1,9.32 26.1,3.07 24.95,1.92
  Top 0.254: JP2.19 24.95,1.91 24.95,1.92
PD0
  Top 0.203: IC2.25 29.9,11 JP2.24
  Top 0.254: JP2.24
PD1
  Top 0.203: JP2.23 31.2,3.07 31.2,5.96 32.38,7.14 32.38,10.72 33.68,12.01
  Top 0.254: JP2.23 | JP2.23 | 33.68,12.01 IC2.26
PD2
  Top 0.203: IC2.27 34.85,11.6 34.85,8.17 32.4,5.72 32.4,4.34
  Top 0.254: JP2.26 32.4,4.34
PD3
  Top 0.203: IC2.28 35.4,11.76 35.4,7.87 33.7,6.22 33.7,3.02 32.45,1.77
  Top 0.254: JP2.25 32.45,1.77 | JP2.25
PD4
  Top 0.203: IC2.29 35.95,11.92 35.95,7.52 34.95,6.52 34.95,4.33
  Top 0.254: JP2.28 34.95,4.33
PD5
  Top 0.203: IC2.30 36.5,12.07 36.5,7.27 36.25,7.02 36.25,3.07 35,1.82
  Top 0.254: 35,1.82 35,1.8 JP2.27
PD6
  Top 0.203: IC2.31 37.55,11.73 37.55,4.32
  Top 0.254: 37.55,4.32 JP2.30
PD7
  Top 0.203: IC2.32 38.8,11.19 38.8,3.02 37.55,1.77
  Top 0.254: JP2.29 37.55,1.77 | JP2.29
PE0
  Top 0.203: IC2.35 42.6,9.51 42.6,4.3
  Top 0.254: 42.6,4.27 42.6,4.3 JP2.34
PE1
  Top 0.203: IC2.36 43.85,8.97 43.85,3.02 42.65,1.82
  Top 0.254: 42.65,1.82 42.64,1.82 JP2.33
PE2
  Top 0.203: IC2.37 45.15,8.37 45.15,4.32
  Top 0.254: 45.15,4.32 JP2.36
PE3
  Top 0.203: IC2.38 46.4,7.83 46.4,3.02 45.2,1.82
  Top 0.254: 45.2,1.82 45.18,1.82 JP2.35
PE4
  Top 0.203: IC2.39 47.65,7.29 47.65,4.32
  Top 0.254: 47.65,4.32 JP2.38
PE5
  Top 0.203: IC2.40 48.95,6.69 48.95,3.02 47.75,1.82
  Top 0.254: JP2.37 47.7,1.8 47.7,1.82 47.75,1.82
PE6
  Top 0.203: IC2.41 50.2,6.15 JP2.40
  Top 0.254: JP2.40
PE7
  Top 0.203: IC2.42 51.5,5.56 51.5,3.07 50.3,1.87
  Top 0.254: 50.3,1.87 50.3,1.86 JP2.39
PF0
  Top 0.203: IC2.45 52.76,6.42 54.1,6.42 55.3,5.22 JP2.44
  Top 0.254: JP2.44 | JP2.44
PF1
  Top 0.203: 55.3,1.82 56.55,3.07 56.55,4.92 54.5,6.97 52.92,6.97 IC2.46
  Top 0.254: 55.3,1.82 JP2.43
PF2
  Top 0.203: IC2.47 53.08,7.52 54.7,7.52 57.8,4.42
  Top 0.254: 57.8,4.42 57.8,4.34 JP2.46
PF3
  Top 0.203: 57.85,1.77 59.1,3.02 59.1,4.92 55.95,8.07 53.23,8.07 IC2.48
  Top 0.254: JP2.45 57.85,1.77 | JP2.45
PF4
  Top 0.203: IC2.49 53.39,8.62 56.15,8.62 60.35,4.42
  Top 0.254: JP2.48 60.35,4.33 60.35,4.42
PF5
  Top 0.203: 60.4,1.77 61.65,3.02 61.65,4.92 57.4,9.17 53.55,9.17 IC2.50
  Top 0.254: JP2.47 60.4,1.77 | JP2.47
PF6
  Top 0.203: 41.65,22.17 54.1,9.72 57.65,9.72 62.9,4.47
  Top 0.254: IC2.51 41.65,22.75 41.65,22.17 | JP2.50 62.9,4.47
PF7
  Top 0.203: 43.3,21.52 54.45,10.37 58.75,10.37 64.15,4.97 64.15,3.02 63,1.87
  Top 0.254: IC2.52 42.56,24.37 42.95,24.37 43.3,24.02 43.3,21.52 | 63,1.87 63,1.86 JP2.49
PH0
  Top 0.203: IC2.55 54.68,38.61 55.93,38.61 56.57,39.24 56.57,41.15 55.35,42.37
  Top 0.254: 55.35,42.37 55.34,42.37 JP1.44
PH1
  Top 0.203: IC2.56 55.24,39.88
  Top 0.254: JP1.43 55.24,39.88
PH2
  Top 0.203: IC2.57 54.03,39.37 54.03,41.15 52.78,42.39
  Top 0.254: 52.78,42.39 JP1.42
PH3
  Top 0.203: IC2.58 52.76,38.8 JP1.41
  Top 0.254: JP1.41
PH4
  Top 0.203: IC2.59 51.49,38.24 51.49,41.15 50.24,42.39
  Top 0.254: 50.24,42.39 JP1.40
PH5
  Top 0.203: IC2.60 50.22,37.68 JP1.39
  Top 0.254: JP1.39
PH6
  Top 0.203: IC2.61 48.95,37.12 48.95,41.15 47.7,42.39
  Top 0.254: 47.7,42.39 JP1.38
PH7
  Top 0.203: IC2.62 47.68,36.55 JP1.37
  Top 0.254: JP1.37
PJ0
  Top 0.203: IC2.65 43.87,34.87 43.87,41.15 42.65,42.37
  Top 0.254: 42.65,42.37 42.64,42.37 JP1.34
PJ1
  Top 0.203: IC2.66 42.6,34.3 JP1.33
  Top 0.254: JP1.33
PJ2
  Top 0.203: IC2.67 41.33,33.74 41.33,41.15 40.13,42.34
  Top 0.254: 40.13,42.34 JP1.32
PJ3
  Top 0.203: IC2.68 40.06,33.18 JP1.31
  Top 0.254: JP1.31
PJ4
  Top 0.203: IC2.69 38.79,32.61 38.79,41.15 37.57,42.37
  Top 0.254: 37.57,42.37 37.56,42.37 JP1.30
PJ5
  Top 0.203: IC2.70 37.52,32.05 JP1.29
  Top 0.254: JP1.29
PJ6
  Top 0.203: IC2.71 36.25,31.49 36.25,31.5 36.7,31.95 36.7,35.28 36.25,35.74 36.25,41.15 JP1.28
  Top 0.254: JP1.28
PJ7
  Top 0.203: JP1.27 35.61,39.88 35.61,35.48 36.09,35 36.09,32.04 IC2.72
  Top 0.254: JP1.27
PK0
  Top 0.203: IC2.75 31.25,34.29 31.17,34.38 31.17,41.17 29.96,42.37 | 29.93,42.37 JP1.24
  Top 0.254: 29.96,42.37 29.93,42.37
PK1
  Top 0.203: 30.02,39.75 JP1.23 | IC2.76 30.02,32.69 30.02,39.75
  Top 0.254: JP1.23 | 30.02,39.75
PK2
  Top 0.203: IC2.77 29.45,32.56 29.45,37.39 28.63,38.21 28.63,41.12 27.41,42.34
  Top 0.254: 27.41,42.34 27.41,42.36 JP1.22
PK3
  Top 0.203: IC2.78 28.97,32.33 28.97,36.67 27.36,38.29 JP1.21
  Top 0.254: JP1.21
PK4
  Top 0.203: IC2.79 28.5,32.1 28.5,35.88 26.09,38.29 26.09,41.15 24.87,42.37
  Top 0.254: 24.87,42.37 24.86,42.37 JP1.20
PK5
  Top 0.203: IC2.80 28.02,31.87 28.02,35.08 24.82,38.29 JP1.19
  Top 0.254: JP1.19
PK6
  Top 0.203: IC2.81 27.54,31.64 27.54,34.29 23.55,38.29 23.55,41.15 22.3,42.39
  Top 0.254: 22.3,42.39 JP1.18
PK7
  Top 0.203: IC2.82 27.07,31.41 27.07,33.66 22.28,38.45 JP1.17
  Top 0.254: JP1.17
PQ0  (via drill 0.3)
  Top 0.203: IC2.85 v24.43,31.92 24.05,32.32 18.55,37.82 18.47,37.9 18.47,41.15 17.22,42.39
  Top 0.254: 17.22,42.39 17.21,42.39 JP1.14
  Bottom 0.254: C17.1 11.27,32.18 11.77,31.68 | 11.77,31.68 12.17,31.28 Q2.1 13.1,31.29 | 11.42,31.28 11.42,31.33 11.77,31.68 | 13.1,31.29 13.1,31.27 | v24.43,31.92 23.85,31.32 13.1,31.32 13.1,31.29
PQ1  (via drill 0.3)
  Top 0.203: IC2.86 25.43,30.22 v25.05,30.22 17.2,38.07 JP1.13
  Top 0.254: v25.05,30.22 24.95,30.22 | JP1.13
  Bottom 0.254: C18.1 5.17,32.18 4.7,31.72 | 4.7,31.72 4.27,31.28 Q2.2 | v25.05,30.22 24.4,30.22 23.95,29.77 6.7,29.77 4.8,31.67 4.75,31.67 4.7,31.72
PQ2
  Top 0.203: IC2.87 25.52,29.42 24.7,29.42 19.9,34.22 | 15.93,35.59 15.93,41.15 14.68,42.39
  Top 0.254: 19.9,34.22 16.75,34.22 15.8,35.17 LED1.C | LED1.C 16,35.52 15.93,35.59 | LED1.C | JP1.12 14.68,42.42 14.68,42.39
PQ3
  Top 0.203: IC2.88 25.56,28.67 24.5,28.67 21.85,31.32 16.5,31.32 15.8,32.02 LED2.C | 14.66,34.01 JP1.11
  Top 0.254: LED2.C | JP1.11 | LED2.C 14.66,34.01
PR0  (via drill 0.3)
  Top 0.254: v21.09,29.07 21.5,29.47 22.64,29.47 IC2.91
  Bottom 0.254: C16.1 12.23,23.28 | 12.23,23.28 12.98,24.18 12.98,24.98 12.96,25 Q1.2 12.98,25.04 | 12.23,23.28 12.25,23.27 15.34,23.32 v21.09,29.07
PR1  (via drill 0.3)
  Top 0.254: IC2.92 22.68,28.72 v22.05,28.72
  Bottom 0.254: Q1.1 12.95,17.02 | C15.1 12.95,17.03 12.95,17.02 | 12.95,17.02 12.95,19.62 v22.05,28.72
RESET  (via drill 0.3)
  Top 0.254: IC2.90 29.4,23.41 v29.4,22.45
  Bottom 0.254: C19.1 30.21,23.15 30.21,23.19 R5.2 29.43,22.45 v29.4,22.45 28.13,21.18 28.13,20.12 27.07,19.06 27.06,19.06 17.81,9.81 | 17.81,9.81 17.77,9.77 7,9.77 6.55,10.22 6.55,11.12 7.45,12.02 7.45,15.62 6.75,16.32 4.8,16.32 X1.5 | 17.81,9.81 17.86,9.76 30.72,9.76 JP4.2
VCC  (via drill 0.3, 0.3 pad 0.3)
  Top 0.203: IC2.74 34.74,32.1 34.74,33.18 32.55,35.37 32.55,39.88 JP1.25 | IC2.24 28.6,10.41 28.6,3.02 27.4,1.82 | JP2.31 41.3,3.02 41.3,10.1 IC2.34 | JP2.41 54,3.02 54,4.92 53.1,5.82 52.65,5.82 IC2.44 | JP2.11 15.9,3.02 15.9,4.78 IC2.14 | IC2.83 26.59,31.18 26.59,33.34 24.37,35.56 v23.18,35.56 | R8.2 55.47,36.42 54.85,35.8 52.58,35.8 IC2.54 | IC2.64 45.14,35.43 JP1.35 | JP1.16 21.01,41.14 21.01,37.72 23.16,35.56 | JP1.45 57.84,38.78 56.44,37.39 R8.2
  Top 0.254: IC2.74 33.29,30.65 v32.66,30.65 | IC2.64 36.79,27.08 v36.23,27.08 | IC2.54 40.33,23.55 v39.76,23.55 | IC2.44 39.05,19.42 v39.05,19.59 | IC2.24 31.38,13.19 v31.95,13.19 | IC2.14 27.85,16.72 v28.48,16.72 | IC2.83 29.41,28.36 v29.93,28.36 | v35.73,16.27 35.7,16.27 35.7,15.7 IC2.34 | JP1.35 | v23.18,35.56 23.16,35.56 | R8.2
  Top 0.305: C23.1 48.78,28.37 | 27.4,1.82 | 27.4,1.82 JP2.21
  Top 0.61: v7.14,28.07 C12.+ | 28.9,19.87 v28.88,19.87 v28.87,19.87 28.9,19.87 | v28.48,16.72 28.9,17.14 | 28.9,17.14 28.9,19.87 | 28.9,19.87 32.02,22.99 v32.02,25.07 32.02,26.7 | v32.66,30.65 32.66,30.62 30.37,28.34 29.93,28.34 v29.93,28.36 30.34,28.36 30.35,28.37 32.02,26.7 | v36.23,27.08 36.22,27.08 35.83,26.7 32.02,26.7 | IC1.4 54.63,25.06 v54.65,25.06 | v39.76,23.55 38.9,22.69 38.9,19.77 39.05,19.61 v39.05,19.59 38.92,19.72 37.25,19.72 35.6,18.07 35.6,16.37 35.7,16.27 v35.73,16.27 35.28,16.72 34.15,16.72 32.05,14.62 | v31.95,13.19 32.05,13.29 32.05,14.62 | 32.05,14.62 31.55,15.12 30.92,15.12 28.9,17.14 | X1.2 11.83,22.69 v14.75,19.77 | C23.1 47.92,28.39 v47.74,28.37
  Top 1.016: C23.1 48.85,28.34 51.59,28.34 | 51.59,28.34 54.61,28.34 54.61,27.68 IC1.4 | 51.59,28.34 51.59,26.5 C11.+ 51.73,26.43 52.07,26.43 R10.2
  Bottom 0.254: C9.1 31.79,30.14 32.12,30.12 v32.66,30.65 | C8.1 35.41,26.55 35.7,26.55 v36.23,27.08 | 38.96,22.95 38.95,22.95 | 38.96,22.95 C7.1 | 38.96,22.95 39.16,22.95 | C6.1 38.35,20.3 v39.05,19.59 | v35.73,16.27 35.73,16.62 35.27,17.08 35.27,17.22 35.28,17.22 C5.1 | C4.1 32.7,13.9 32.66,13.9 v31.95,13.19 | v28.48,16.72 27.78,16.02 C3.1 | C10.1 30.7,27.61 30.68,27.61 v29.93,28.36 | R5.1 31.91,24.93 v32.02,25.07 | R4.1 28.16,19.16 v28.87,19.87 28.87,20.72 R3.1 | v23.18,35.56 21.59,35.56 R6.2 21.59,35.51 R7.2
  Bottom 0.305: v39.76,23.55 39.75,23.54 39.75,23.52 39.53,23.52 38.96,22.95 | IC3.16 50.15,17.96 54.65,22.47 v54.65,25.06
  Bottom 0.61: v7.14,28.07 6.05,26.97 X1.2 | v14.75,19.77 16.15,19.77 26.85,30.47 28.85,30.47 29.95,29.37 29.95,28.37 v29.93,28.36 | X1.2 | X1.2 6.05,22.67 | IC3.16 50.15,15.17 50.65,14.67 51.8,14.67 C25.1 | v39.76,23.55 v39.76,23.56 39.75,23.57 44.55,28.37 v47.74,28.37
VDD
  Top 1.016: IC1.3 60.93,30 60.95,30.02 60.94,30.03 60.94,31.67 | 60.94,31.67 C22.+ | 60.94,31.67 63.3,31.67 C24.1 63.48,39.31 JP1.49 JP1.50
